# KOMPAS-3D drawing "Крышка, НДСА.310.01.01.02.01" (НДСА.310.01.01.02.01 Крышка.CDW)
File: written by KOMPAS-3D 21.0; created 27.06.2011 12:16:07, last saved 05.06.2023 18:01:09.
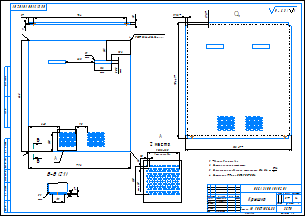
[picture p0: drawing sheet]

Sheet 1: A2, landscape

Document properties: Полное имя файла: НДСА.310.01.01.02.01 Крышка.m3d; Автор: Гривенко; Организация: esto; 248056315393: <item xmlns="http://appius.ru/pdm" xmlns:xs="http://www.w3.org/2001/XMLSchema" xmlns:xsi="http://www.w3.org/2001/XMLSchema-instance" xsi:type="item">  <element xmlns:d2p1="http://v8.1c.ru/8.1/data/enterprise/current-config" xsi:type="d2p1:CatalogRef.aps_Элемен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; Масса: 5.77; Знак неуказанной шероховатости: 4; Параметр неуказанной шероховатости: Ra 6,3; 354686828211: <item xmlns="http://appius.ru/pdm" xmlns:xs="http://www.w3.org/2001/XMLSchema" xmlns:xsi="http://www.w3.org/2001/XMLSchema-instance" xsi:type="item">  <element xmlns:d2p1="http://v8.1c.ru/8.1/data/enterprise/current-config" xsi:type="d2p1:CatalogRef.aps_Элемен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; 306624613344: <item xmlns="http://appius.ru/pdm" xmlns:xs="http://www.w3.org/2001/XMLSchema" xmlns:xsi="http://www.w3.org/2001/XMLSchema-instance" xsi:type="item">  <element xmlns:d2p1="http://v8.1c.ru/8.1/data/enterprise/current-config" xsi:type="d2p1:CatalogRef.aps_Элемен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; 250045921003: <item xmlns="http://appius.ru/pdm" xmlns:xs="http://www.w3.org/2001/XMLSchema" xmlns:xsi="http://www.w3.org/2001/XMLSchema-instance" xsi:type="item">  <element xmlns:d2p1="http://v8.1c.ru/8.1/data/enterprise/current-config" xsi:type="d2p1:CatalogRef.aps_Элемен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; 250045921103: <item xmlns="http://appius.ru/pdm" xmlns:xs="http://www.w3.org/2001/XMLSchema" xmlns:xsi="http://www.w3.org/2001/XMLSchema-instance" xsi:type="item">  <element xmlns:d2p1="http://v8.1c.ru/8.1/data/enterprise/current-config" xsi:type="d2p1:CatalogRef.aps_Элемен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; 250045921203: <item xmlns="http://appius.ru/pdm" xmlns:xs="http://www.w3.org/2001/XMLSchema" xmlns:xsi="http://www.w3.org/2001/XMLSchema-instance" xsi:type="item">  <element xmlns:d2p1="http://v8.1c.ru/8.1/data/enterprise/current-config" xsi:type="d2p1:CatalogRef.aps_Элемен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; 353738473720: <item xmlns="http://appius.ru/pdm" xmlns:xs="http://www.w3.org/2001/XMLSchema" xmlns:xsi="http://www.w3.org/2001/XMLSchema-instance" xsi:type="item">  <element xmlns:d2p1="http://v8.1c.ru/8.1/data/enterprise/current-config" xsi:type="d2p1:CatalogRef.aps_Элемен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; 353738473820: <item xmlns="http://appius.ru/pdm" xmlns:xs="http://www.w3.org/2001/XMLSchema" xmlns:xsi="http://www.w3.org/2001/XMLSchema-instance" xsi:type="item">  <element xmlns:d2p1="http://v8.1c.ru/8.1/data/enterprise/current-config" xsi:type="d2p1:CatalogRef.aps_Элемен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; 353738473920: <item xmlns="http://appius.ru/pdm" xmlns:xs="http://www.w3.org/2001/XMLSchema" xmlns:xsi="http://www.w3.org/2001/XMLSchema-instance" xsi:type="item">  <element xmlns:d2p1="http://v8.1c.ru/8.1/data/enterprise/current-config" xsi:type="d2p1:CatalogRef.aps_Элемен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; 327716828516: <item xmlns="http://appius.ru/pdm" xmlns:xs="http://www.w3.org/2001/XMLSchema" xmlns:xsi="http://www.w3.org/2001/XMLSchema-instance" xsi:type="item">  <element xmlns:d2p1="http://v8.1c.ru/8.1/data/enterprise/current-config" xsi:type="d2p1:CatalogRef.aps_Элемен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; 327716828716: <item xmlns="http://appius.ru/pdm" xmlns:xs="http://www.w3.org/2001/XMLSchema" xmlns:xsi="http://www.w3.org/2001/XMLSchema-instance" xsi:type="item">  <element xmlns:d2p1="http://v8.1c.ru/8.1/data/enterprise/current-config" xsi:type="d2p1:CatalogRef.aps_Элемен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; 272228359789: <item xmlns="http://appius.ru/pdm" xmlns:xs="http://www.w3.org/2001/XMLSchema" xmlns:xsi="http://www.w3.org/2001/XMLSchema-instance" xsi:type="item">  <element xmlns:d2p1="http://v8.1c.ru/8.1/data/enterprise/current-config" xsi:type="d2p1:CatalogRef.aps_Элемен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; PDM_ITEMXDTO: <item xmlns="http://appius.ru/pdm" xmlns:xs="http://www.w3.org/2001/XMLSchema" xmlns:xsi="http://www.w3.org/2001/XMLSchema-instance" xsi:type="item">  <element xmlns:d2p1="http://v8.1c.ru/8.1/data/enterprise/current-config" xsi:type="d2p1:CatalogRef.aps_Элемен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; PDM_DOCXDTO: <item xmlns="http://appius.ru/pdm" xmlns:xs="http://www.w3.org/2001/XMLSchema" xmlns:xsi="http://www.w3.org/2001/XMLSchema-instance" xsi:type="item">  <element xmlns:d2p1="http://v8.1c.ru/8.1/data/enterprise/current-config" xsi:type="d2p1:CatalogRef.aps_Элемен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; PLM_CDWXDTO: <item xmlns="http://appius.ru/pdm" xmlns:xs="http://www.w3.org/2001/XMLSchema" xmlns:xsi="http://www.w3.org/2001/XMLSchema-instance" xsi:type="item">  <element xmlns:d2p1="http://v8.1c.ru/8.1/data/enterprise/current-config" xsi:type="d2p1:CatalogRef.aps_Элемен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; PDM_DRAWINGXDTO: <item xmlns="http://appius.ru/pdm" xmlns:xs="http://www.w3.org/2001/XMLSchema" xmlns:xsi="http://www.w3.org/2001/XMLSchema-instance" xsi:type="item">  <element xmlns:d2p1="http://v8.1c.ru/8.1/data/enterprise/current-config" xsi:type="d2p1:CatalogRef.aps_Элемен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

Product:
- Part/product: Крышка  | designation НДСА.310.01.01.02.01
    Масса: 5.766009
    Форматы листов документа: A2
    additional columns: <item xmlns="http://appius.ru/pdm" xmlns:xs="http://www.w3.org/2001/XMLSchema" x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; <item xmlns="http://appius.ru/pdm" xmlns:xs="http://www.w3.org/2001/XMLSchema" x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; <item xmlns="http://appius.ru/pdm" xmlns:xs="http://www.w3.org/2001/XMLSchema" x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; <item xmlns="http://appius.ru/pdm" xmlns:xs="http://www.w3.org/2001/XMLSchema" x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; <item xmlns="http://appius.ru/pdm" xmlns:xs="http://www.w3.org/2001/XMLSchema" x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; <item xmlns="http://appius.ru/pdm" xmlns:xs="http://www.w3.org/2001/XMLSchema" x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; <item xmlns="http://appius.ru/pdm" xmlns:xs="http://www.w3.org/2001/XMLSchema" x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; <item xmlns="http://appius.ru/pdm" xmlns:xs="http://www.w3.org/2001/XMLSchema" x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

Title block, sheet 1: Наименование: Крышка; designation: НДСА.310.01.01.02.01; Материал: Сталь 10  ГОСТ 1050-88; Масса: 5,77; scale: 1:4; Количество листов документа: 1; organisation: ЭСТО; Форматы листов документа: A2; stored path: C:\Documents and Settings\grivenko\Мои документы\Николай\Работа\Крышка\Крышка _ БПКЖ.737.13.00.00.01-01.cdw; Разработал: Степаненкова; Проверил: Горностаев; Утвердил: Белецкий; Разработал, date: 05.06.2023

Views: Спереди 1, Спереди, Вид 4, Развертка, Разрез 5, Проекционный вид 6, Выносной элемент 7, Разрез Б-Б, Выносной элемент А, Выносной элемент
Referenced files in C:\Users\cherbakova\Desktop\PLM\: НДСА.875.03.00.00.01 Крышка.m3d
Referenced files in C:\PLM\: НДСА.310.01.01.02.01 Крышка.m3d
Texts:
  ГОСТ 5264-80-У4-
  тип.
  Линейный размер
  Радиальный размер
  в шах.порядке
  шаг 10
  Ra 6,3
  Ra 6,3 ( )
  НДСА.310.01.01.02.01 Крышка
Dimensions and other numbers on the sheet: 796; 868; 4; 152; 228; 132; 30,5; 1; 240; 150; 95; 832,47; 904,47; 19,12; 11; 37; 724; 20; 9; 2 места; 10; 10х12=125; 110; 1:4; 5,77; 05.06.2023

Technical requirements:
  *Размер для справок.
  Острые кромки притупить.
  Неуказанные предельные отклонения H14 h14,    IT14 2 .
  Остальные Т.Т.- по ОСТ4.ГО.070.014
